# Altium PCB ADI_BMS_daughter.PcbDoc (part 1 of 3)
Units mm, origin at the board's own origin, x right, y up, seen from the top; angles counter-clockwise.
Board outline 140 x 50 mm, 4 copper layers (Top Layer, Layer 1, Layer 2, Bottom Layer), stack 1.586 mm thick; 306 components, 232 nets, 866 pads, 333 vias.
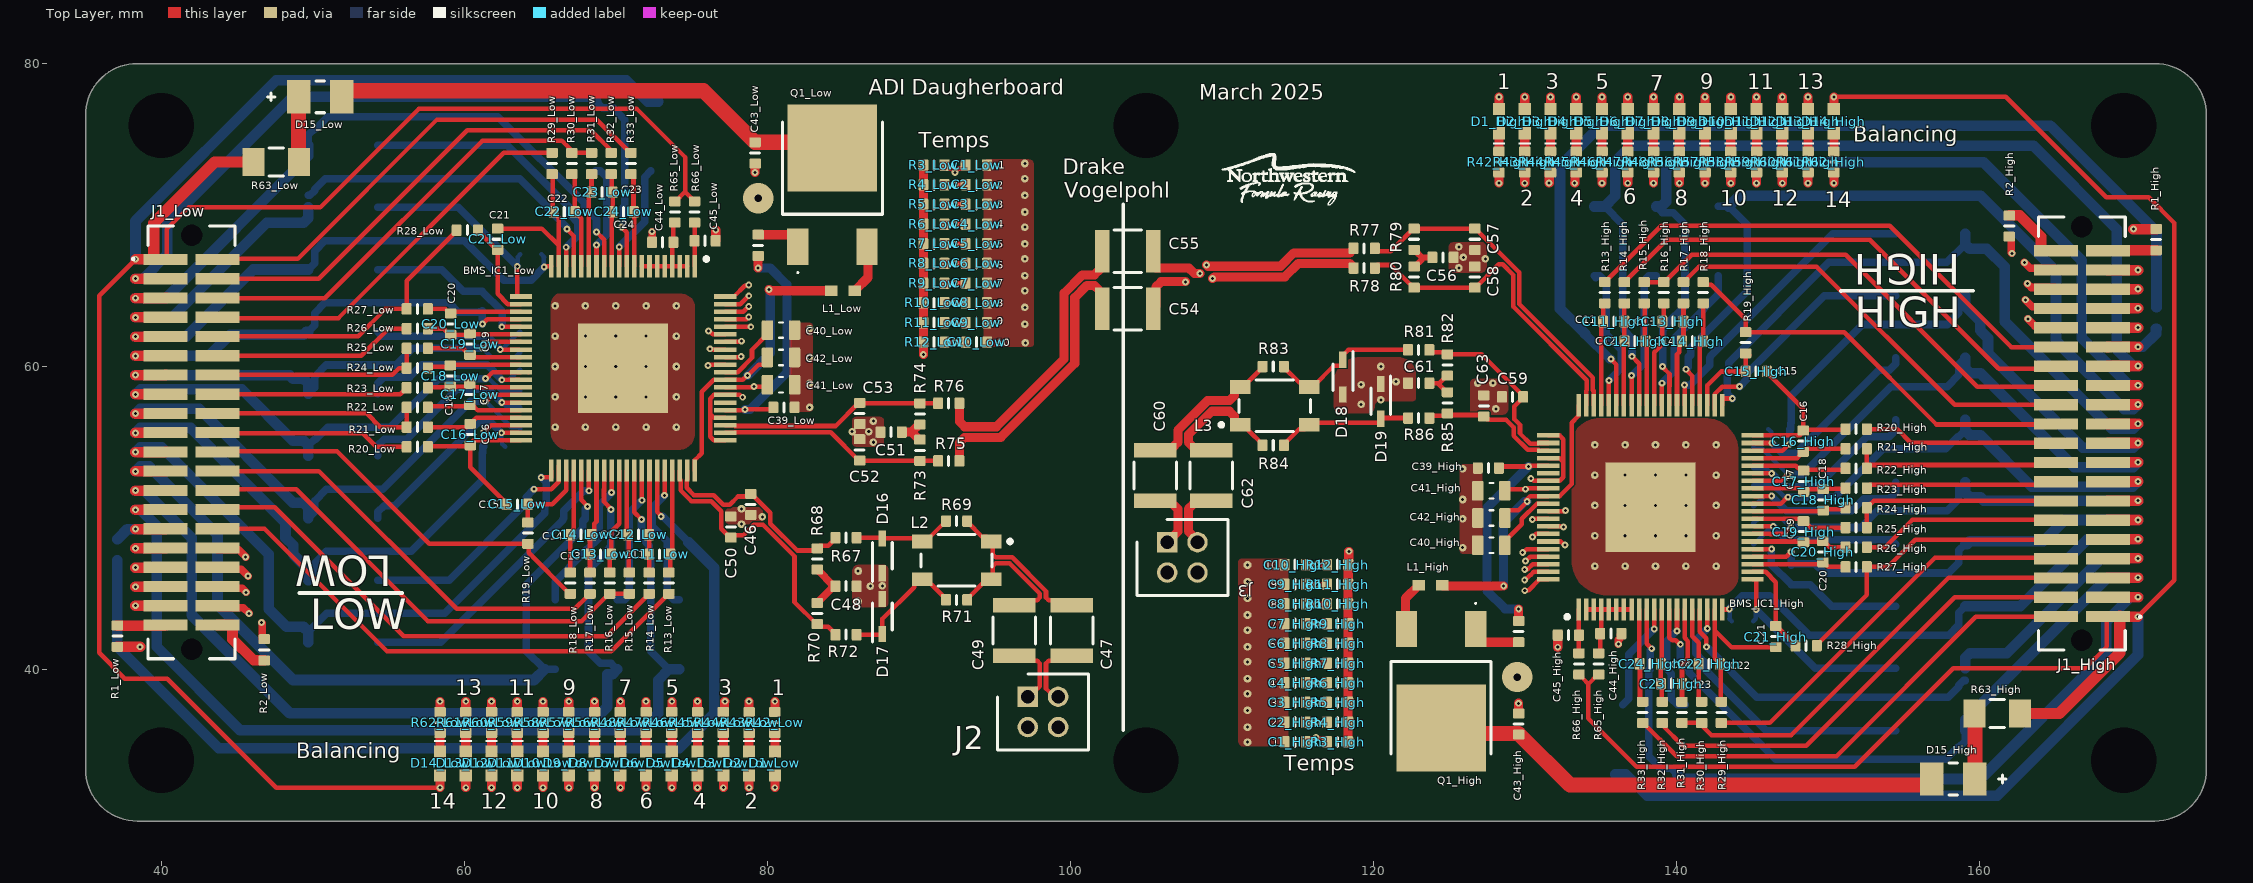
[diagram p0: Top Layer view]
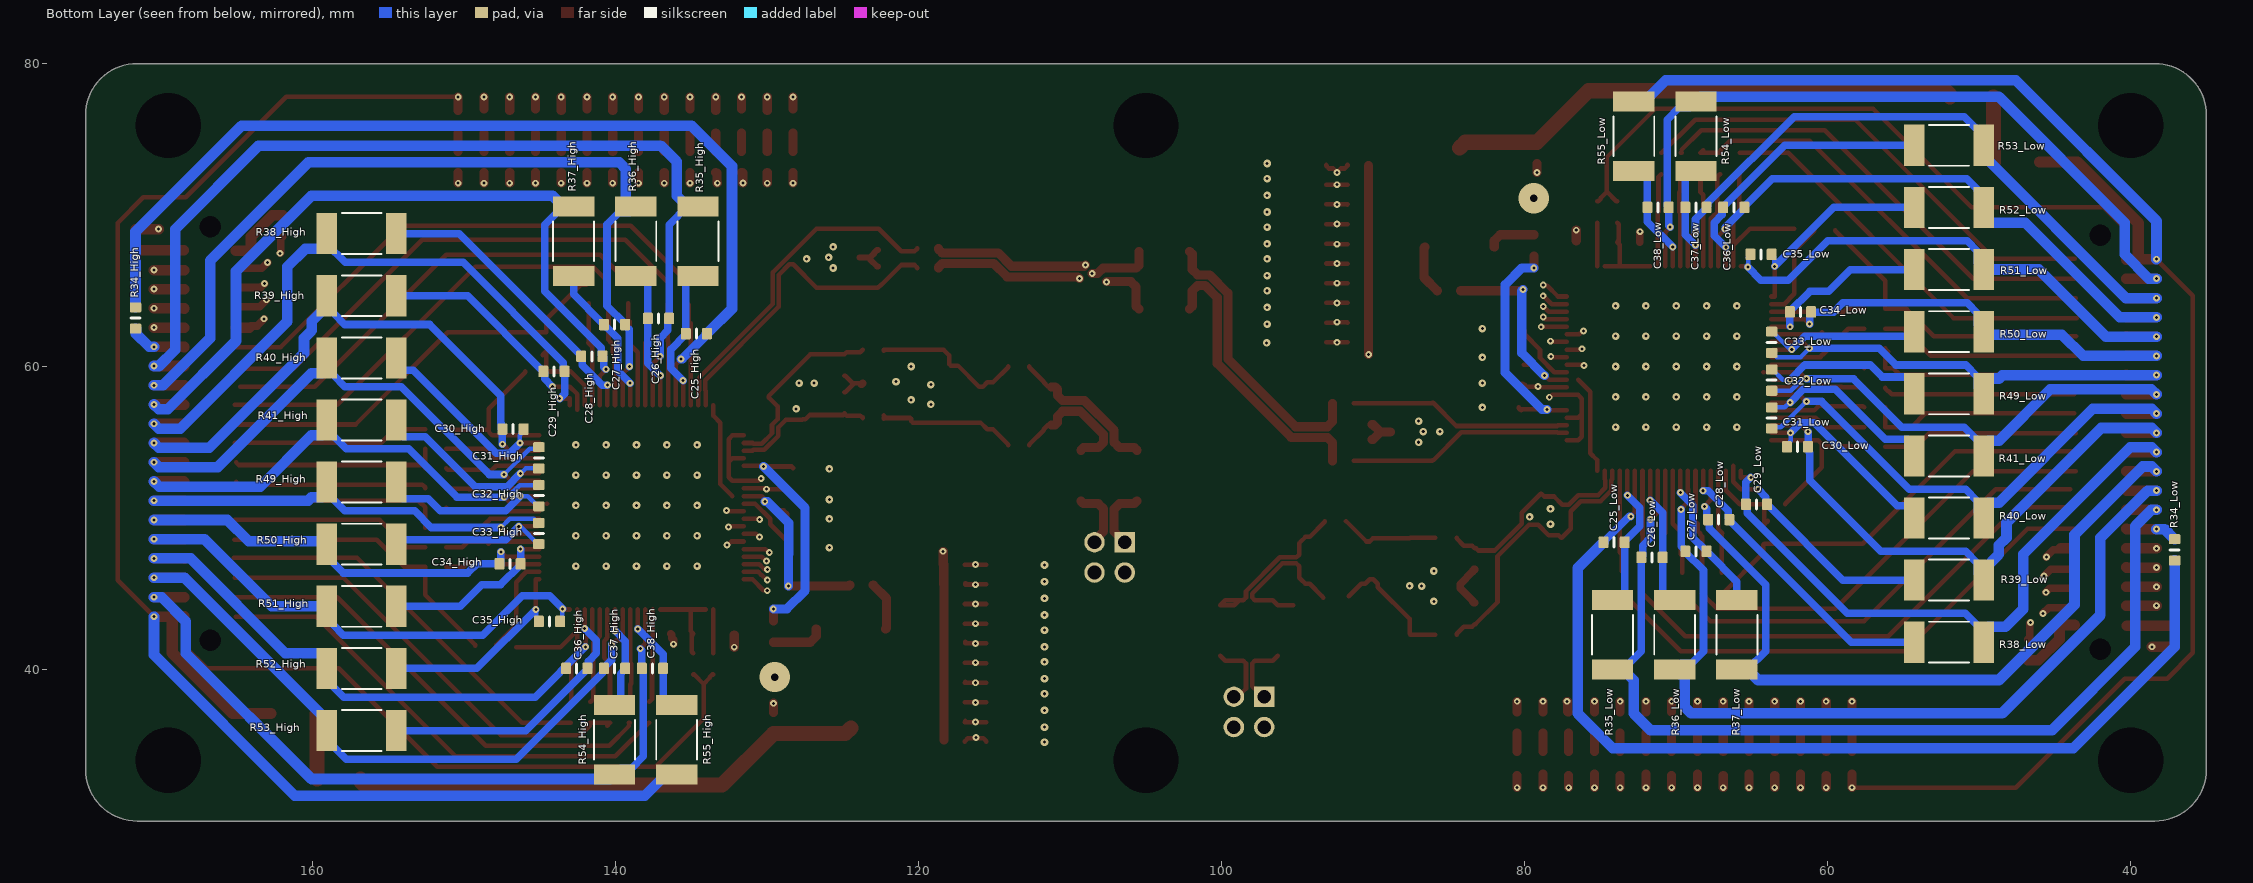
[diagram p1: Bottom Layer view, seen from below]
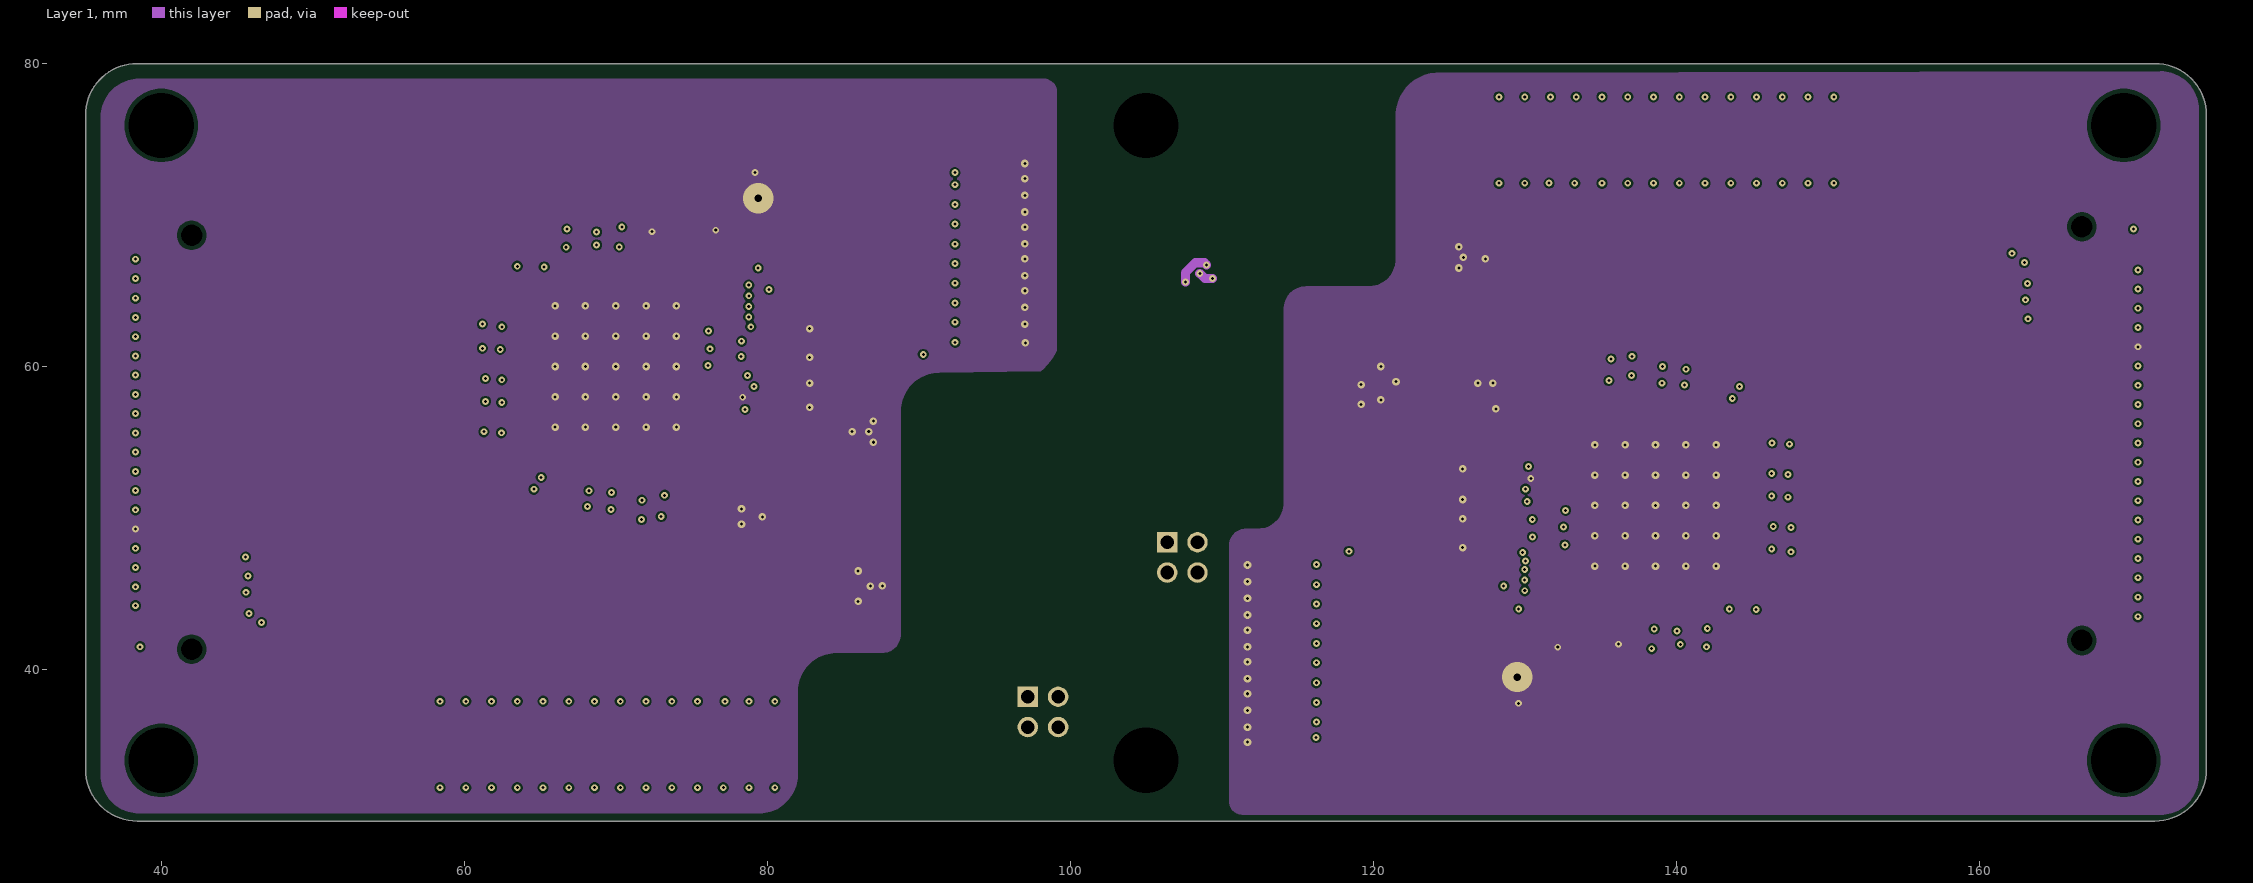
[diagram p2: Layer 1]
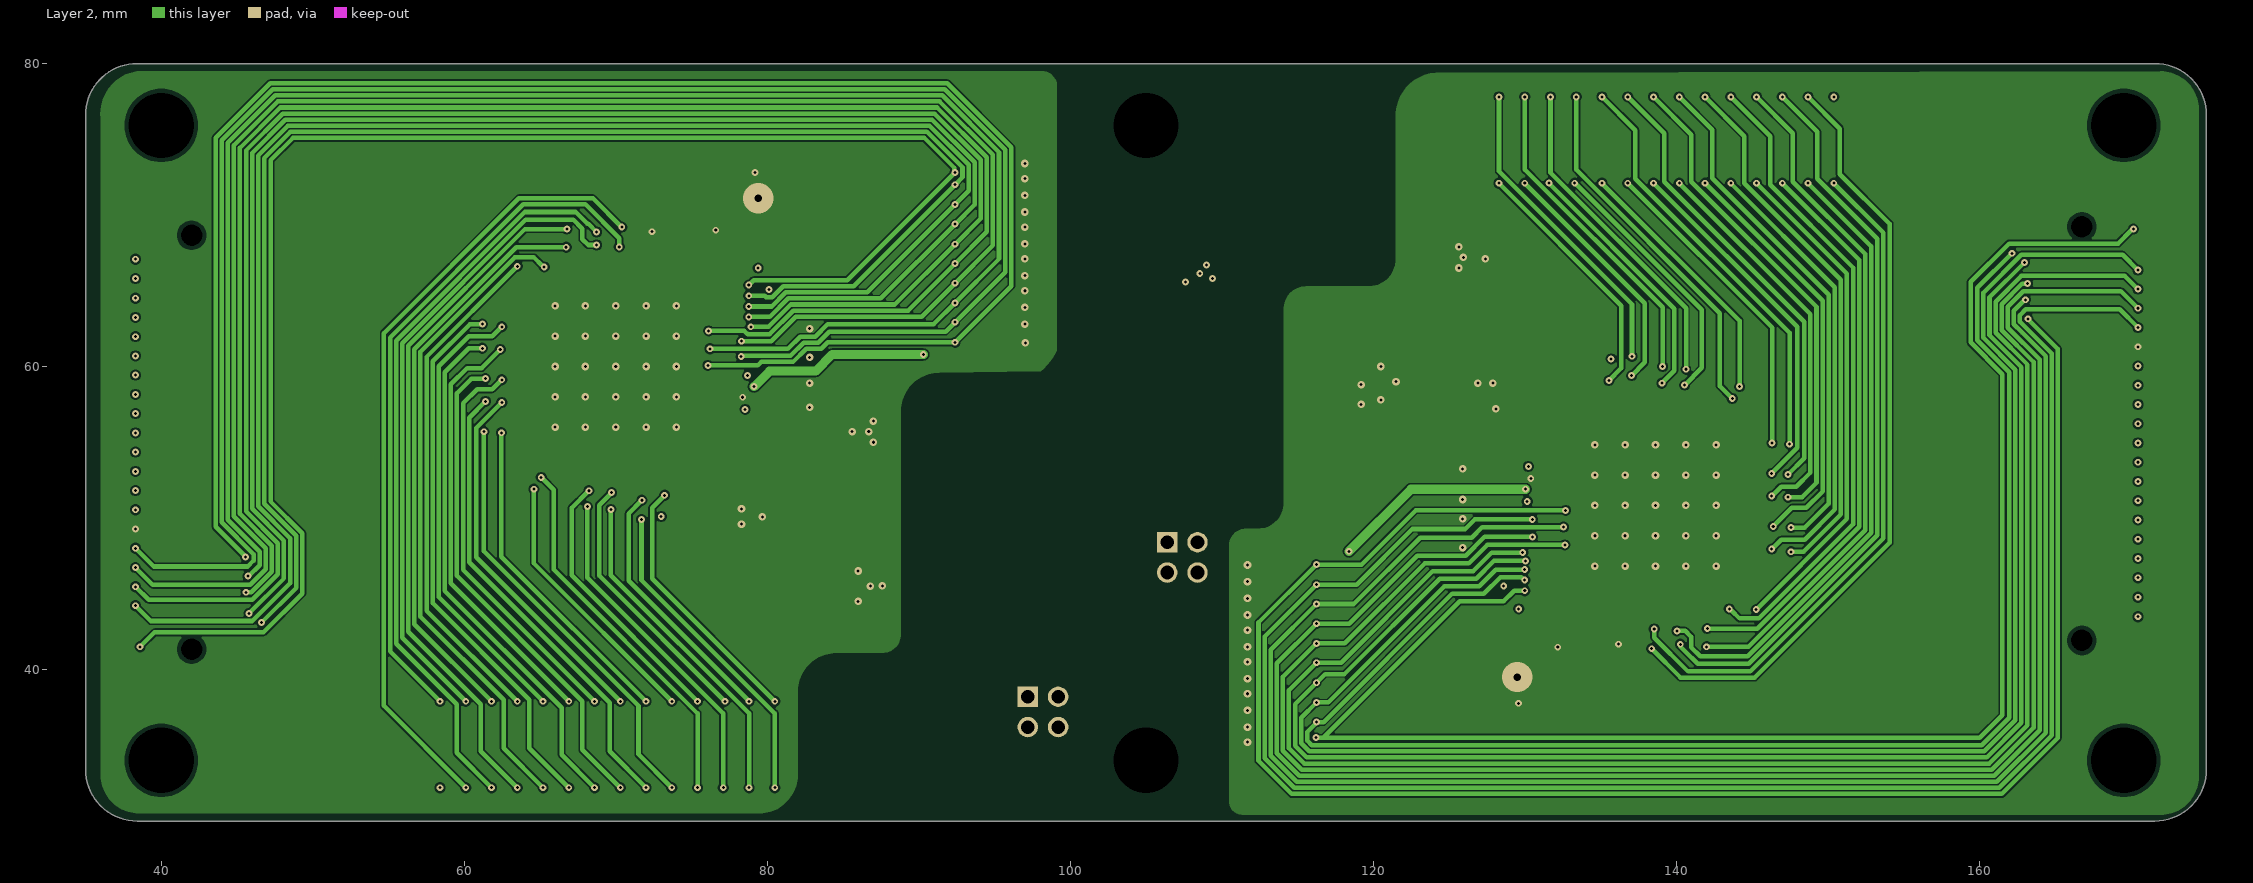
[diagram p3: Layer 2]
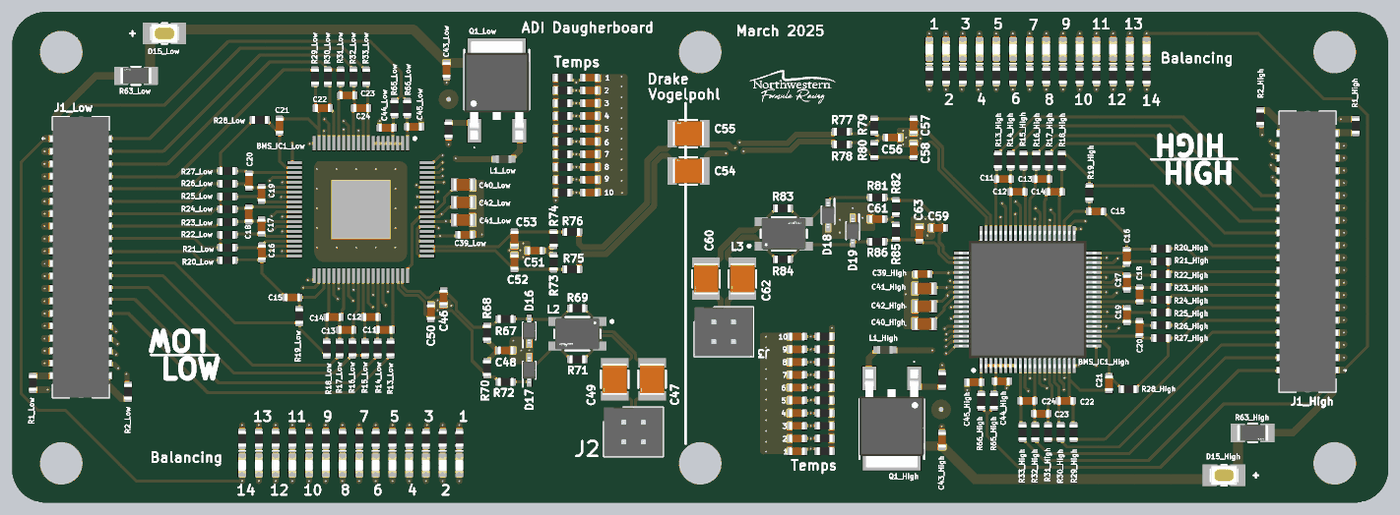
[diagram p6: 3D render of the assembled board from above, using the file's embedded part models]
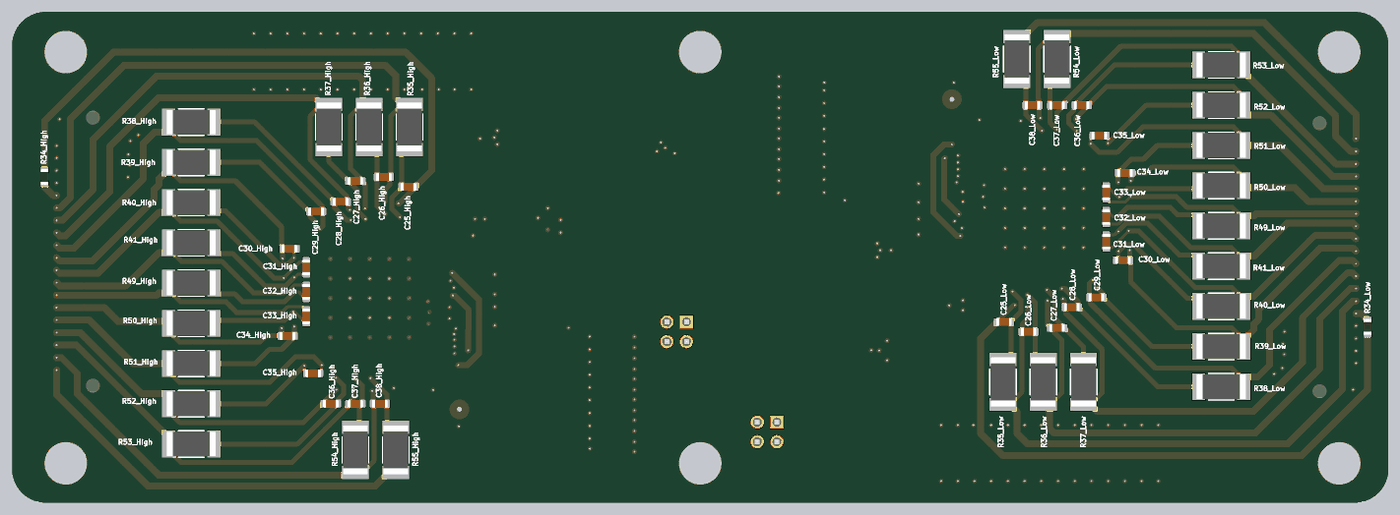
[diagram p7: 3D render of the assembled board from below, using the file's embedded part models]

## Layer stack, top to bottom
Top Solder: solder mask 0.0102, Solder Resist, Dk 3.5
Top Layer: signal copper 0.035
Dielectric 1: prepreg 0.2104, PP-023, Dk 4.5
Layer 1: signal copper 0.0152
Core: core 1.065, FR-4, Dk 4.8
Layer 2: signal copper 0.0152
Dielectric 2: prepreg 0.2104, PP-023, Dk 4.5
Bottom Layer: signal copper 0.035
Bottom Solder: solder mask 0.0102, Solder Resist, Dk 3.5

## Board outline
35,33.414 35,76.586 cw(c38.414,76.586) 38.414,80 171.586,80 cw(c171.586,76.586) 175,76.586 175,33.414 cw(c171.586,33.414) 171.586,30 38.414,30 cw(c38.414,33.414)

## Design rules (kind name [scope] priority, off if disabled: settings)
BoardOutlineClearance [All] p1: gap=0.2 ignorepadtopadclearanceinfootprint=FALSE
Clearance [All] p1: gap=0.102 ignorepadtopadclearanceinfootprint=FALSE except(0.127: Arc-Via Track-Via SMDPad-Via THPad-Via Via-Via Via-Fill Via-Poly Via-Region Via-Text; 0.25: Arc-Hole Track-Hole SMDPad-Hole THPad-Hole Via-Hole Fill-Hole Poly-Hole Region-Hole Text-Hole)
ComponentClearance [All] p1: gap=0.102 collisioncheckmode=3 verticalgap=0.102 showdistances=TRUE
DiffPairsRouting [All] p1: maxlimit=0.102 minlimit=0.102 mostfreqgap=0.102 toplayer_minwidth=0.102 toplayer_maxwidth=1816.048 toplayer_prefwidth=0.102 midlayer1_minwidth=0.102 midlayer1_maxwidth=1816.048 midlayer1_prefwidth=0.102 midlayer2_minwidth=0.102 midlayer2_maxwidth=1816.048 midlayer2_prefwidth=0.102 bottomlayer_minwidth=0.102 bottomlayer_maxwidth=1816.048 bottomlayer_prefwidth=0.102 maxuncoupledlength=12.7
Height [All] p1: minheight=0 maxheight=1816.048 prefheight=12.7
HoleSize [All] p1: absolutevalues=TRUE maxlimit=6.3 minlimit=0.2 maxpercent=80.000 minpercent=20.000
HoleToHoleClearance [All] p1: gap=0.25 allowstackedmicrovias=FALSE
MinimumAnnularRing [All] p1: minimumring=0.076
MinimumSolderMaskSliver [All] p1: minsoldermaskwidth=0
PlaneClearance [All] p1: clearance=0.102
PlaneConnect PlaneConnectPowerPads [InPadClass('PowerPads')] p1: planeconnectstyle=Direct reliefexpansion=0.508 reliefentries=4 reliefconductorwidth=0.254 reliefairgap=0.254
PlaneConnect [All] p2: pad.planeconnectstyle=Relief pad.reliefexpansion=0.3 pad.reliefentries=4 pad.reliefconductorwidth=0.102 pad.reliefairgap=0.102 via.planeconnectstyle=Direct via.reliefexpansion=0.3 via.reliefentries=4 via.reliefconductorwidth=0.127 via.reliefairgap=0.127
PolygonConnect PolygonConnectPowerPads [All vs (InPadClass('PowerPads'))] p1: connectstyle=Direct reliefconductorwidth=0.254 reliefentries=4 polygonreliefangle="90 Angle" airgapwidth=0.254
PolygonConnect [All] p2: thpad.connectstyle=Relief thpad.reliefconductorwidth=0.102 thpad.reliefentries=4 thpad.polygonreliefangle="90 Angle" thpad.airgapwidth=0.102 smdpad.connectstyle=Relief smdpad.reliefconductorwidth=0.102 smdpad.reliefentries=4 smdpad.polygonreliefangle="90 Angle" smdpad.airgapwidth=0.102 via.connectstyle=Direct via.reliefconductorwidth=0.127 via.reliefentries=4 via.polygonreliefangle="90 Angle" via.airgapwidth=0.127
RoutingVias [All] p1: holewidth=0.2 width=0.45 viastyle="Through Hole" minholewidth=0.2 minwidth=0.45 maxholewidth=6.3 maxwidth=6.55
SilkToSilkClearance [All] p1: silktosilkclearance=0
SilkToSolderMaskClearance [IsPad] p1: minsilkscreentomaskgap=0.102 clearancetoexposedcopper=TRUE
SolderMaskExpansion [All] p1: expansion=0.075 istentingtop=FALSE
Width [All] p1: maxlimit=1816.048 minlimit=0.102 preferedwidth=0.3 minimp=50.000000 maximp=50.000000 favimp=50.000000
20 further rules are at their usual default settings.

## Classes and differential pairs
channel class 1_ADI_BMS_daughter_half: High Low
component class Low: "           " BMS_IC1_Low C1_Low C2_Low C3_Low C4_Low C5_Low C6_Low C7_Low C8_Low C9_Low C10_Low C11_Low C12_Low C13_Low C14_Low C15_Low C16_Low C17_Low C18_Low C19_Low C20_Low C21_Low C22_Low C23_Low C24_Low C25_Low C26_Low C27_Low C28_Low C29_Low C30_Low C31_Low C32_Low C33_Low C34_Low C35_Low C36_Low C37_Low C38_Low C39_Low C40_Low C41_Low C42_Low C43_Low C44_Low C45_Low D1_Low D2_Low D3_Low D4_Low D5_Low D6_Low D7_Low D8_Low D9_Low D10_Low D11_Low D12_Low D13_Low D14_Low D15_Low J1_Low L1_Low Q1_Low R1_Low R2_Low R3_Low R4_Low R5_Low R6_Low R7_Low R8_Low R9_Low R10_Low R11_Low R12_Low R13_Low R14_Low R15_Low R16_Low R17_Low R18_Low R19_Low R20_Low R21_Low R22_Low R23_Low R24_Low R25_Low R26_Low R27_Low R28_Low R29_Low R30_Low R31_Low R32_Low R33_Low R34_Low R35_Low R36_Low R37_Low R38_Low R39_Low R40_Low R41_Low R42_Low R43_Low R44_Low R45_Low R46_Low R47_Low R48_Low R49_Low R50_Low R51_Low R52_Low R53_Low R54_Low R55_Low R56_Low R57_Low R58_Low R59_Low R60_Low R61_Low R62_Low R63_Low R65_Low R66_Low
component class High: "           " BMS_IC1_High C1_High C2_High C3_High C4_High C5_High C6_High C7_High C8_High C9_High C10_High C11_High C12_High C13_High C14_High C15_High C16_High C17_High C18_High C19_High C20_High C21_High C22_High C23_High C24_High C25_High C26_High C27_High C28_High C29_High C30_High C31_High C32_High C33_High C34_High C35_High C36_High C37_High C38_High C39_High C40_High C41_High C42_High C43_High C44_High C45_High D1_High D2_High D3_High D4_High D5_High D6_High D7_High D8_High D9_High D10_High D11_High D12_High D13_High D14_High D15_High J1_High L1_High Q1_High R1_High R2_High R3_High R4_High R5_High R6_High R7_High R8_High R9_High R10_High R11_High R12_High R13_High R14_High R15_High R16_High R17_High R18_High R19_High R20_High R21_High R22_High R23_High R24_High R25_High R26_High R27_High R28_High R29_High R30_High R31_High R32_High R33_High R34_High R35_High R36_High R37_High R38_High R39_High R40_High R41_High R42_High R43_High R44_High R45_High R46_High R47_High R48_High R49_High R50_High R51_High R52_High R53_High R54_High R55_High R56_High R57_High R58_High R59_High R60_High R61_High R62_High R63_High R65_High R66_High
component class 0_ADI_BMS_daughter_Overview: C46 C47 C48 C49 C50 C51 C52 C53 C54 C55 C56 C57 C58 C59 C60 C61 C62 C63 D16 D17 D18 D19 J2 J3 L2 L3 R67 R68 R69 R70 R71 R72 R73 R74 R75 R77 R78 R79 R80 R81 R82 R83 R84 R85 R86
differential pair IB_Low_Intr: +IB_Low_Intr_P -IB_Low_Intr_N
differential pair IB_High_Iso: +IB_High_Iso_P -IB_High_Iso_N
differential pair IB_High_CMC: +IB_High_CMC_P -IB_High_CMC_N
differential pair IA_Low_Iso: +IA_Low_Iso_P -IA_Low_Iso_N
differential pair IA_Low_CMC: +IA_Low_CMC_P -IA_Low_CMC_N
differential pair IA_High_Intr: +IA_High_Intr_P -IA_High_Intr_N
differential pair IB_Out: +IB_Out_P -IB_Out_N
differential pair IB_Low: +IB_Low_P -IB_Low_N
differential pair IB_High: +IB_High_P -IB_High_N
differential pair IA_Out: +IA_Out_P -IA_Out_N
differential pair IA_Low: +IA_Low_P -IA_Low_N
differential pair IA_High: +IA_High_P -IA_High_N

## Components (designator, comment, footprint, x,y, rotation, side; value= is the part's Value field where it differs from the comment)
BMS_IC1_High "ADBMS6830BCSWZ" QFP50P1400X1400X160-81N 138.3,50.7 r90 top (schematic designator BMS_IC1)
BMS_IC1_Low "ADBMS6830BCSWZ" QFP50P1400X1400X160-81N 70.479,59.871 r270 top locked (schematic designator BMS_IC1)
C1_High "0.1u" CAPC0603(1608)100_L 114.85,35.225 r180 top (schematic designator C1)
C1_Low "0.1u" CAPC0603(1608)100_L 93.8,73.3 r0 top (schematic designator C1)
C2_High "0.1u" CAPC0603(1608)100_L 114.85,36.525 r180 top (schematic designator C2)
C2_Low "0.1u" CAPC0603(1608)100_L 93.8,72 r0 top (schematic designator C2)
C3_High "0.1u" CAPC0603(1608)100_L 114.85,37.825 r180 top (schematic designator C3)
C3_Low "0.1u" CAPC0603(1608)100_L 93.8,70.7 r0 top (schematic designator C3)
C4_High "0.1u" CAPC0603(1608)100_L 114.85,39.125 r180 top (schematic designator C4)
C4_Low "0.1u" CAPC0603(1608)100_L 93.8,69.4 r0 top (schematic designator C4)
C5_High "0.1u" CAPC0603(1608)100_L 114.85,40.425 r180 top (schematic designator C5)
C5_Low "0.1u" CAPC0603(1608)100_L 93.8,68.1 r0 top (schematic designator C5)
C6_High "0.1u" CAPC0603(1608)100_L 114.85,41.725 r180 top (schematic designator C6)
C6_Low "0.1u" CAPC0603(1608)100_L 93.8,66.8 r0 top (schematic designator C6)
C7_High "0.1u" CAPC0603(1608)100_L 114.85,43.025 r180 top (schematic designator C7)
C7_Low "0.1u" CAPC0603(1608)100_L 93.8,65.5 r0 top (schematic designator C7)
C8_High "0.1u" CAPC0603(1608)100_L 114.85,44.325 r180 top (schematic designator C8)
C8_Low "0.1u" CAPC0603(1608)100_L 93.8,64.2 r0 top (schematic designator C8)
C9_High "0.1u" CAPC0603(1608)100_L 114.85,45.625 r180 top (schematic designator C9)
C9_Low "0.1u" CAPC0603(1608)100_L 93.8,62.9 r0 top (schematic designator C9)
C10_High "0.1u" CAPC0603(1608)100_L 114.85,46.925 r180 top (schematic designator C10)
C10_Low "0.1u" CAPC0603(1608)100_L 93.8,61.6 r0 top (schematic designator C10)
C11_High "C1608X7R2A103K080AA" CAPC0603(1608)100_L 135.879,62.971 r0 top value=10n (schematic designator C11)
C11_Low "C1608X7R2A103K080AA" CAPC0603(1608)100_L 72.9,47.6 r180 top value=10n (schematic designator C11)
C12_High "C1608X7R2A103K080AA" CAPC0603(1608)100_L 137.279,61.671 r0 top value=10n (schematic designator C12)
C12_Low "C1608X7R2A103K080AA" CAPC0603(1608)100_L 71.5,48.9 r180 top value=10n (schematic designator C12)
C13_High "C1608X7R2A103K080AA" CAPC0603(1608)100_L 139.779,62.971 r0 top value=10n (schematic designator C13)
C13_Low "C1608X7R2A103K080AA" CAPC0603(1608)100_L 69,47.6 r180 top value=10n (schematic designator C13)
C14_High "C1608X7R2A103K080AA" CAPC0603(1608)100_L 141.079,61.671 r0 top value=10n (schematic designator C14)
C14_Low "C1608X7R2A103K080AA" CAPC0603(1608)100_L 67.7,48.9 r180 top value=10n (schematic designator C14)
C15_High "C1608X7R2A103K080AA" CAPC0603(1608)100_L 145.279,59.671 r0 top value=10n (schematic designator C15)
C15_Low "C1608X7R2A103K080AA" CAPC0603(1608)100_L 63.5,50.9 r180 top value=10n (schematic designator C15)
C16_High "C1608X7R2A103K080AA" CAPC0603(1608)100_L 148.379,55.071 r270 top value=10n (schematic designator C16)
C16_Low "C1608X7R2A103K080AA" CAPC0603(1608)100_L 60.4,55.5 r90 top value=10n (schematic designator C16)
C17_High "C1608X7R2A103K080AA" CAPC0603(1608)100_L 148.404,52.421 r270 top value=10n (schematic designator C17)
C17_Low "C1608X7R2A103K080AA" CAPC0603(1608)100_L 60.375,58.15 r90 top value=10n (schematic designator C17)
C18_High "C1608X7R2A103K080AA" CAPC0603(1608)100_L 149.7,51.2 r270 top value=10n (schematic designator C18)
C18_Low "C1608X7R2A103K080AA" CAPC0603(1608)100_L 59.079,59.371 r90 top value=10n (schematic designator C18)
C19_High "C1608X7R2A103K080AA" CAPC0603(1608)100_L 148.4,49.1 r270 top value=10n (schematic designator C19)
C19_Low "C1608X7R2A103K080AA" CAPC0603(1608)100_L 60.379,61.471 r90 top value=10n (schematic designator C19)
C20_High "C1608X7R2A103K080AA" CAPC0603(1608)100_L 149.679,47.771 r270 top value=10n (schematic designator C20)
C20_Low "C1608X7R2A103K080AA" CAPC0603(1608)100_L 59.1,62.8 r90 top value=10n (schematic designator C20)
C21_High "C1608X7R2A103K080AA" CAPC0603(1608)100_L 146.579,42.171 r270 top value=10n (schematic designator C21)
C21_Low "C1608X7R2A103K080AA" CAPC0603(1608)100_L 62.2,68.4 r90 top value=10n (schematic designator C21)
C22_High "C1608X7R2A103K080AA" CAPC0603(1608)100_L 142.179,40.371 r180 top value=10n (schematic designator C22)
C22_Low "C1608X7R2A103K080AA" CAPC0603(1608)100_L 66.6,70.2 r0 top value=10n (schematic designator C22)
C23_High "C1608X7R2A103K080AA" CAPC0603(1608)100_L 139.679,39.071 r180 top value=10n (schematic designator C23)
C23_Low "C1608X7R2A103K080AA" CAPC0603(1608)100_L 69.1,71.5 r0 top value=10n (schematic designator C23)
C24_High "C1608X7R2A103K080AA" CAPC0603(1608)100_L 138.279,40.371 r180 top value=10n (schematic designator C24)
C24_Low "C1608X7R2A103K080AA" CAPC0603(1608)100_L 70.5,70.2 r0 top value=10n (schematic designator C24)
C25_High "0.1u" CAPC0603(1608)100_L 134.679,62.171 r0 bottom (schematic designator C25)
C25_Low "0.1u" CAPC0603(1608)100_L 74.1,48.4 r180 bottom (schematic designator C25)
C26_High "0.1u" CAPC0603(1608)100_L 137.179,63.171 r0 bottom (schematic designator C26)
C26_Low "0.1u" CAPC0603(1608)100_L 71.6,47.4 r180 bottom (schematic designator C26)
C27_High "0.1u" CAPC0603(1608)100_L 140.079,62.771 r0 bottom (schematic designator C27)
C27_Low "0.1u" CAPC0603(1608)100_L 68.7,47.8 r180 bottom (schematic designator C27)
C28_High "0.1u" CAPC0603(1608)100_L 141.579,60.671 r0 bottom (schematic designator C28)
C28_Low "0.1u" CAPC0603(1608)100_L 67.2,49.9 r180 bottom (schematic designator C28)
C29_High "0.1u" CAPC0603(1608)100_L 144.079,59.671 r0 bottom (schematic designator C29)
C29_Low "0.1u" CAPC0603(1608)100_L 64.7,50.9 r180 bottom (schematic designator C29)
C30_High "0.1u" CAPC0603(1608)100_L 146.779,55.871 r180 bottom (schematic designator C30)
C30_Low "0.1u" CAPC0603(1608)100_L 62,54.7 r0 bottom (schematic designator C30)
C31_High "0.1u" CAPC0603(1608)100_L 145.079,53.971 r270 bottom (schematic designator C31)
C31_Low "0.1u" CAPC0603(1608)100_L 63.7,56.6 r90 bottom (schematic designator C31)
C32_High "0.1u" CAPC0603(1608)100_L 145.079,51.471 r270 bottom (schematic designator C32)
C32_Low "0.1u" CAPC0603(1608)100_L 63.7,59.1 r90 bottom (schematic designator C32)
C33_High "0.1u" CAPC0603(1608)100_L 145.079,48.971 r270 bottom (schematic designator C33)
C33_Low "0.1u" CAPC0603(1608)100_L 63.7,61.6 r90 bottom (schematic designator C33)
C34_High "0.1u" CAPC0603(1608)100_L 146.979,46.971 r180 bottom (schematic designator C34)
C34_Low "0.1u" CAPC0603(1608)100_L 61.8,63.6 r0 bottom (schematic designator C34)
C35_High "0.1u" CAPC0603(1608)100_L 144.379,43.171 r0 bottom (schematic designator C35)
C35_Low "0.1u" CAPC0603(1608)100_L 64.4,67.4 r180 bottom (schematic designator C35)
C36_High "0.1u" CAPC0603(1608)100_L 142.579,40.071 r180 bottom (schematic designator C36)
C36_Low "0.1u" CAPC0603(1608)100_L 66.2,70.5 r0 bottom (schematic designator C36)
C37_High "0.1u" CAPC0603(1608)100_L 140.079,40.071 r180 bottom (schematic designator C37)
C37_Low "0.1u" CAPC0603(1608)100_L 68.7,70.5 r0 bottom (schematic designator C37)
C38_High "0.1u" CAPC0603(1608)100_L 137.579,40.071 r180 bottom (schematic designator C38)
C38_Low "0.1u" CAPC0603(1608)100_L 71.2,70.5 r0 bottom (schematic designator C38)
C39_High "C1608X7R2A103K080AA" CAPC0603(1608)100_L 127.6,53.3 r0 top value=10n (schematic designator C39)
C39_Low "C1608X7R2A103K080AA" CAPC0603(1608)100_L 81.1,57.3 r180 top value=10n (schematic designator C39)
C40_High "1u" CAPC0805(2012)145_L 127.8,48.2 r0 top (schematic designator C40)
C40_Low "1u" CAPC0805(2012)145_L 80.9,62.4 r180 top (schematic designator C40)
C41_High "1u" CAPC0805(2012)145_L 127.8,51.8 r0 top (schematic designator C41)
C41_Low "1u" CAPC0805(2012)145_L 80.9,58.8 r180 top (schematic designator C41)
C42_High "1u" CAPC0805(2012)145_L 127.8,50 r0 top (schematic designator C42)
C42_Low "1u" CAPC0805(2012)145_L 80.9,60.6 r180 top (schematic designator C42)
C43_High "C1608X7R2A103K080AA" CAPC0603(1608)100_L 129.6,36.4 r90 top value=10n (schematic designator C43)
C43_Low "C1608X7R2A103K080AA" CAPC0603(1608)100_L 79.2,74.1 r270 top value=10n (schematic designator C43)
C44_High "C1608X7R2A103K080AA" CAPC0603(1608)100_L 135.679,42.371 r180 top value=10n (schematic designator C44)
C44_Low "C1608X7R2A103K080AA" CAPC0603(1608)100_L 73.1,68.2 r0 top value=10n (schematic designator C44)
C45_High "C1608X7R2A103K080AA" CAPC0603(1608)100_L 132.879,42.271 r180 top value=10n (schematic designator C45)
C45_Low "C1608X7R2A103K080AA" CAPC0603(1608)100_L 75.9,68.3 r0 top value=10n (schematic designator C45)
C46 "CGA3E2C0G2A221J080AA" CAPC0603(1608)100_L 78.9,50.9 r270 top value=220pF
C47 "22n" FP-C3225-250-0_4-IPC_B 100.1,42.575 r270 top
C48 "0.1u" CAPC0603(1608)100_L 85.2,45.5 r0 top
C49 "22n" FP-C3225-250-0_4-IPC_B 96.3,42.575 r270 top
C50 "CGA3E2C0G2A221J080AA" CAPC0603(1608)100_L 77.6,49.4 r270 top value=220pF
C51 "0.1u" CAPC0603(1608)100_L 88.179,55.671 r0 top
C52 "CGA3E2C0G2A221J080AA" CAPC0603(1608)100_L 86.1,54.5 r90 top value=220pF
C53 "CGA3E2C0G2A221J080AA" CAPC0603(1608)100_L 86.1,56.9 r90 top value=220pF
C54 "22n" FP-C3225-250-0_4-IPC_B 103.8,63.8 r180 top
C55 "22n" FP-C3225-250-0_4-IPC_B 103.8,67.6 r180 top
C56 "0.1u" CAPC0603(1608)100_L 124.6,67.2 r0 top
C57 "CGA3E2C0G2A221J080AA" CAPC0603(1608)100_L 126.7,68.4 r270 top value=220pF
C58 "CGA3E2C0G2A221J080AA" CAPC0603(1608)100_L 126.7,65.9 r270 top value=220pF
C59 "CGA3E2C0G2A221J080AA" CAPC0603(1608)100_L 129.2,58 r180 top value=220pF
C60 "22n" FP-C3225-250-0_4-IPC_B 105.6,52.8 r270 top
C61 "0.1u" CAPC0603(1608)100_L 123,58.9 r180 top
C62 "22n" FP-C3225-250-0_4-IPC_B 109.3,52.8 r270 top
C63 "CGA3E2C0G2A221J080AA" CAPC0603(1608)100_L 127.3,57.4 r270 top value=220pF
D1_High "150060RS75000" WL-SMCW_0603_150060xx75000 128.3,76.2 r90 top (schematic designator D1)
D1_Low "150060RS75000" WL-SMCW_0603_150060xx75000 80.5,33.8 r270 top (schematic designator D1)
D2_High "150060RS75000" WL-SMCW_0603_150060xx75000 130,76.2 r90 top (schematic designator D2)
D2_Low "150060RS75000" WL-SMCW_0603_150060xx75000 78.8,33.8 r270 top (schematic designator D2)
D3_High "150060RS75000" WL-SMCW_0603_150060xx75000 131.7,76.2 r90 top (schematic designator D3)
D3_Low "150060RS75000" WL-SMCW_0603_150060xx75000 77.1,33.8 r270 top (schematic designator D3)
D4_High "150060RS75000" WL-SMCW_0603_150060xx75000 133.4,76.2 r90 top (schematic designator D4)
D4_Low "150060RS75000" WL-SMCW_0603_150060xx75000 75.4,33.8 r270 top (schematic designator D4)
D5_High "150060RS75000" WL-SMCW_0603_150060xx75000 135.1,76.2 r90 top (schematic designator D5)
D5_Low "150060RS75000" WL-SMCW_0603_150060xx75000 73.7,33.8 r270 top (schematic designator D5)
D6_High "150060RS75000" WL-SMCW_0603_150060xx75000 136.8,76.2 r90 top (schematic designator D6)
D6_Low "150060RS75000" WL-SMCW_0603_150060xx75000 72,33.8 r270 top (schematic designator D6)
D7_High "150060RS75000" WL-SMCW_0603_150060xx75000 138.5,76.2 r90 top (schematic designator D7)
D7_Low "150060RS75000" WL-SMCW_0603_150060xx75000 70.3,33.8 r270 top (schematic designator D7)
D8_High "150060RS75000" WL-SMCW_0603_150060xx75000 140.2,76.2 r90 top (schematic designator D8)
D8_Low "150060RS75000" WL-SMCW_0603_150060xx75000 68.6,33.8 r270 top (schematic designator D8)
D9_High "150060RS75000" WL-SMCW_0603_150060xx75000 141.9,76.2 r90 top (schematic designator D9)
D9_Low "150060RS75000" WL-SMCW_0603_150060xx75000 66.9,33.8 r270 top (schematic designator D9)
D10_High "150060RS75000" WL-SMCW_0603_150060xx75000 143.6,76.2 r90 top (schematic designator D10)
D10_Low "150060RS75000" WL-SMCW_0603_150060xx75000 65.2,33.8 r270 top (schematic designator D10)
D11_High "150060RS75000" WL-SMCW_0603_150060xx75000 145.3,76.2 r90 top (schematic designator D11)
D11_Low "150060RS75000" WL-SMCW_0603_150060xx75000 63.5,33.8 r270 top (schematic designator D11)
D12_High "150060RS75000" WL-SMCW_0603_150060xx75000 147,76.2 r90 top (schematic designator D12)
D12_Low "150060RS75000" WL-SMCW_0603_150060xx75000 61.8,33.8 r270 top (schematic designator D12)
D13_High "150060RS75000" WL-SMCW_0603_150060xx75000 148.7,76.2 r90 top (schematic designator D13)
D13_Low "150060RS75000" WL-SMCW_0603_150060xx75000 60.1,33.8 r270 top (schematic designator D13)
D14_High "150060RS75000" WL-SMCW_0603_150060xx75000 150.4,76.2 r90 top (schematic designator D14)
D14_Low "150060RS75000" WL-SMCW_0603_150060xx75000 58.4,33.8 r270 top (schematic designator D14)
D15_High "Amber LED" FP-CLM3C-AKW-MFG 158.279,32.771 r180 top (schematic designator D15)
D15_Low "Amber LED" FP-CLM3C-AKW-MFG 50.5,77.8 r0 top (schematic designator D15)
D16 "SD12C-01FTG" SOD2613X114N 87.6,47.5 r90 top
D17 "SD12C-01FTG" SOD2613X114N 87.6,43.5 r90 top
D18 "SD12C-01FTG" SOD2613X114N 118,59.3 r270 top
D19 "SD12C-01FTG" SOD2613X114N 120.5,57.7 r270 top
J1_High "TFM-120-02-L-D-A-TR" TFM12002LDATR 166.779,55.571 r90 top (schematic designator J1)
J1_Low "TFM-120-02-L-D-A-TR" TFM12002LDATR 42,55 r270 top locked (schematic designator J1)
J2 "DF11-4DP-2DSA_01_" SHDR4W50P200_2X2_600X500X660P 97.2,38.2 r180 top
J3 "DF11-4DP-2DSA_01_" SHDR4W50P200_2X2_600X500X660P 106.4,48.4 r180 top
L1_High "742792693" SMD-0603 123.779,45.571 r0 top (schematic designator L1)
L1_Low "742792693" SMD-0603 85,65 r180 top (schematic designator L1)
L2 "DLW43SH101XK2L" FP-DLW43-0_2-t2_6-e0_6-MFG 92.5,47.2 r180 top
L3 "DLW43SH101XK2L" FP-DLW43-0_2-t2_6-e0_6-MFG 113.5,57.4 r0 top
Q1_High "MJD31CAJ" MJD31CAJ 124.479,38.571 r180 top (schematic designator Q1)
Q1_Low "MJD31CAJ" MJD31CAJ 84.3,72 r0 top (schematic designator Q1)
R1_High "RMCF0603ZT0R00" RESC0603(1608)_L 171.679,68.371 r270 top value=0 (schematic designator R1)
R1_Low "RMCF0603ZT0R00" RESC0603(1608)_L 37.1,42.2 r90 top value=0 (schematic designator R1)
R2_High "RMCF0603ZT0R00" RESC0603(1608)_L 161.979,69.271 r90 top value=0 (schematic designator R2)
R2_Low "RMCF0603ZT0R00" RESC0603(1608)_L 46.8,41.3 r270 top value=0 (schematic designator R2)
R3_High "RT0603BRD0710KL" RESC0603(1608)_L 117.65,35.225 r0 top value=10k (schematic designator R3)
R3_Low "RT0603BRD0710KL" RESC0603(1608)_L 91,73.3 r180 top value=10k (schematic designator R3)
R4_High "RT0603BRD0710KL" RESC0603(1608)_L 117.65,36.525 r0 top value=10k (schematic designator R4)
R4_Low "RT0603BRD0710KL" RESC0603(1608)_L 91,72 r180 top value=10k (schematic designator R4)
R5_High "RT0603BRD0710KL" RESC0603(1608)_L 117.65,37.825 r0 top value=10k (schematic designator R5)
R5_Low "RT0603BRD0710KL" RESC0603(1608)_L 91,70.7 r180 top value=10k (schematic designator R5)
R6_High "RT0603BRD0710KL" RESC0603(1608)_L 117.65,39.125 r0 top value=10k (schematic designator R6)
R6_Low "RT0603BRD0710KL" RESC0603(1608)_L 91,69.4 r180 top value=10k (schematic designator R6)
R7_High "RT0603BRD0710KL" RESC0603(1608)_L 117.65,40.425 r0 top value=10k (schematic designator R7)
R7_Low "RT0603BRD0710KL" RESC0603(1608)_L 91,68.1 r180 top value=10k (schematic designator R7)
R8_High "RT0603BRD0710KL" RESC0603(1608)_L 117.65,41.725 r0 top value=10k (schematic designator R8)
R8_Low "RT0603BRD0710KL" RESC0603(1608)_L 91,66.8 r180 top value=10k (schematic designator R8)
R9_High "RT0603BRD0710KL" RESC0603(1608)_L 117.65,43.025 r0 top value=10k (schematic designator R9)
R9_Low "RT0603BRD0710KL" RESC0603(1608)_L 91,65.5 r180 top value=10k (schematic designator R9)
R10_High "RT0603BRD0710KL" RESC0603(1608)_L 117.65,44.325 r0 top value=10k (schematic designator R10)
R10_Low "RT0603BRD0710KL" RESC0603(1608)_L 91,64.2 r180 top value=10k (schematic designator R10)
R11_High "RT0603BRD0710KL" RESC0603(1608)_L 117.65,45.625 r0 top value=10k (schematic designator R11)
R11_Low "RT0603BRD0710KL" RESC0603(1608)_L 91,62.9 r180 top value=10k (schematic designator R11)
R12_High "RT0603BRD0710KL" RESC0603(1608)_L 117.65,46.925 r0 top value=10k (schematic designator R12)
R12_Low "RT0603BRD0710KL" RESC0603(1608)_L 91,61.6 r180 top value=10k (schematic designator R12)
R13_High "ESR03EZPF2000" RESC0603(1608)_L 135.279,64.871 r270 top value=200 (schematic designator R13)
R13_Low "ESR03EZPF2000" RESC0603(1608)_L 73.5,45.7 r90 top value=200 (schematic designator R13)
R14_High "ESR03EZPF2000" RESC0603(1608)_L 136.579,64.871 r270 top value=200 (schematic designator R14)
R14_Low "ESR03EZPF2000" RESC0603(1608)_L 72.2,45.7 r90 top value=200 (schematic designator R14)
R15_High "ESR03EZPF2000" RESC0603(1608)_L 137.879,64.871 r270 top value=200 (schematic designator R15)
R15_Low "ESR03EZPF2000" RESC0603(1608)_L 70.9,45.7 r90 top value=200 (schematic designator R15)
R16_High "ESR03EZPF2000" RESC0603(1608)_L 139.179,64.871 r270 top value=200 (schematic designator R16)
R16_Low "ESR03EZPF2000" RESC0603(1608)_L 69.6,45.7 r90 top value=200 (schematic designator R16)
R17_High "ESR03EZPF2000" RESC0603(1608)_L 140.479,64.871 r270 top value=200 (schematic designator R17)
R17_Low "ESR03EZPF2000" RESC0603(1608)_L 68.3,45.7 r90 top value=200 (schematic designator R17)
R18_High "ESR03EZPF2000" RESC0603(1608)_L 141.779,64.871 r270 top value=200 (schematic designator R18)
R18_Low "ESR03EZPF2000" RESC0603(1608)_L 67,45.7 r90 top value=200 (schematic designator R18)
R19_High "ESR03EZPF2000" RESC0603(1608)_L 144.579,61.571 r270 top value=200 (schematic designator R19)
R19_Low "ESR03EZPF2000" RESC0603(1608)_L 64.2,49 r90 top value=200 (schematic designator R19)
R20_High "ESR03EZPF2000" RESC0603(1608)_L 151.879,55.871 r180 top value=200 (schematic designator R20)
R20_Low "ESR03EZPF2000" RESC0603(1608)_L 56.9,54.7 r0 top value=200 (schematic designator R20)
R21_High "ESR03EZPF2000" RESC0603(1608)_L 151.879,54.571 r180 top value=200 (schematic designator R21)
R21_Low "ESR03EZPF2000" RESC0603(1608)_L 56.9,56 r0 top value=200 (schematic designator R21)
R22_High "ESR03EZPF2000" RESC0603(1608)_L 151.879,53.271 r180 top value=200 (schematic designator R22)
R22_Low "ESR03EZPF2000" RESC0603(1608)_L 56.9,57.3 r0 top value=200 (schematic designator R22)
R23_High "ESR03EZPF2000" RESC0603(1608)_L 151.879,51.971 r180 top value=200 (schematic designator R23)
R23_Low "ESR03EZPF2000" RESC0603(1608)_L 56.9,58.6 r0 top value=200 (schematic designator R23)
R24_High "ESR03EZPF2000" RESC0603(1608)_L 151.879,50.671 r180 top value=200 (schematic designator R24)
R24_Low "ESR03EZPF2000" RESC0603(1608)_L 56.9,59.9 r0 top value=200 (schematic designator R24)
R25_High "ESR03EZPF2000" RESC0603(1608)_L 151.879,49.371 r180 top value=200 (schematic designator R25)
R25_Low "ESR03EZPF2000" RESC0603(1608)_L 56.9,61.2 r0 top value=200 (schematic designator R25)
R26_High "ESR03EZPF2000" RESC0603(1608)_L 151.879,48.071 r180 top value=200 (schematic designator R26)
R26_Low "ESR03EZPF2000" RESC0603(1608)_L 56.9,62.5 r0 top value=200 (schematic designator R26)
R27_High "ESR03EZPF2000" RESC0603(1608)_L 151.879,46.771 r180 top value=200 (schematic designator R27)
R27_Low "ESR03EZPF2000" RESC0603(1608)_L 56.9,63.8 r0 top value=200 (schematic designator R27)
R28_High "ESR03EZPF2000" RESC0603(1608)_L 148.579,41.571 r180 top value=200 (schematic designator R28)
R28_Low "ESR03EZPF2000" RESC0603(1608)_L 60.2,69 r0 top value=200 (schematic designator R28)
R29_High "ESR03EZPF2000" RESC0603(1608)_L 142.979,37.171 r90 top value=200 (schematic designator R29)
R29_Low "ESR03EZPF2000" RESC0603(1608)_L 65.8,73.4 r270 top value=200 (schematic designator R29)
R30_High "ESR03EZPF2000" RESC0603(1608)_L 141.679,37.171 r90 top value=200 (schematic designator R30)
R30_Low "ESR03EZPF2000" RESC0603(1608)_L 67.1,73.4 r270 top value=200 (schematic designator R30)
R31_High "ESR03EZPF2000" RESC0603(1608)_L 140.379,37.171 r90 top value=200 (schematic designator R31)
R31_Low "ESR03EZPF2000" RESC0603(1608)_L 68.4,73.4 r270 top value=200 (schematic designator R31)
R32_High "ESR03EZPF2000" RESC0603(1608)_L 139.079,37.171 r90 top value=200 (schematic designator R32)
R32_Low "ESR03EZPF2000" RESC0603(1608)_L 69.7,73.4 r270 top value=200 (schematic designator R32)
R33_High "ESR03EZPF2000" RESC0603(1608)_L 137.779,37.171 r90 top value=200 (schematic designator R33)
R33_Low "ESR03EZPF2000" RESC0603(1608)_L 71,73.4 r270 top value=200 (schematic designator R33)
R34_High "RMCF0603ZT0R00" RESC0603(1608)_L 171.7,63.2 r270 bottom value=0 (schematic designator R34)
R34_Low "RMCF0603ZT0R00" RESC0603(1608)_L 37.1,47.9 r90 bottom value=0 (schematic designator R34)
R35_High "RMCP2010FT20R0" RESC5025X70N 134.579,68.271 r270 bottom value=20 (schematic designator R35)
R35_Low "RMCP2010FT20R0" RESC5025X70N 74.2,42.3 r90 bottom value=20 (schematic designator R35)
R36_High "RMCP2010FT20R0" RESC5025X70N 138.679,68.271 r270 bottom value=20 (schematic designator R36)
R36_Low "RMCP2010FT20R0" RESC5025X70N 70.1,42.3 r90 bottom value=20 (schematic designator R36)
R37_High "RMCP2010FT20R0" RESC5025X70N 142.779,68.271 r270 bottom value=20 (schematic designator R37)
R37_Low "RMCP2010FT20R0" RESC5025X70N 66,42.3 r90 bottom value=20 (schematic designator R37)
R38_High "RMCP2010FT20R0" RESC5025X70N 156.779,68.771 r180 bottom value=20 (schematic designator R38)
R38_Low "RMCP2010FT20R0" RESC5025X70N 52,41.8 r0 bottom value=20 (schematic designator R38)
R39_High "RMCP2010FT20R0" RESC5025X70N 156.779,64.671 r180 bottom value=20 (schematic designator R39)
R39_Low "RMCP2010FT20R0" RESC5025X70N 52,45.9 r0 bottom value=20 (schematic designator R39)
R40_High "RMCP2010FT20R0" RESC5025X70N 156.779,60.571 r180 bottom value=20 (schematic designator R40)
R40_Low "RMCP2010FT20R0" RESC5025X70N 52,50 r0 bottom value=20 (schematic designator R40)
R41_High "RMCP2010FT20R0" RESC5025X70N 156.779,56.471 r180 bottom value=20 (schematic designator R41)
R41_Low "RMCP2010FT20R0" RESC5025X70N 52,54.1 r0 bottom value=20 (schematic designator R41)
R42_High "100" RESC0603(1608)_L 128.3,73.5 r270 top (schematic designator R42)
R42_Low "100" RESC0603(1608)_L 80.5,36.5 r90 top (schematic designator R42)
R43_High "100" RESC0603(1608)_L 130,73.5 r270 top (schematic designator R43)
R43_Low "100" RESC0603(1608)_L 78.8,36.5 r90 top (schematic designator R43)
R44_High "100" RESC0603(1608)_L 131.7,73.5 r270 top (schematic designator R44)
R44_Low "100" RESC0603(1608)_L 77.1,36.5 r90 top (schematic designator R44)
R45_High "100" RESC0603(1608)_L 133.4,73.5 r270 top (schematic designator R45)
R45_Low "100" RESC0603(1608)_L 75.4,36.5 r90 top (schematic designator R45)
R46_High "100" RESC0603(1608)_L 135.1,73.5 r270 top (schematic designator R46)
R46_Low "100" RESC0603(1608)_L 73.7,36.5 r90 top (schematic designator R46)
R47_High "100" RESC0603(1608)_L 136.8,73.5 r270 top (schematic designator R47)
R47_Low "100" RESC0603(1608)_L 72,36.5 r90 top (schematic designator R47)
R48_High "100" RESC0603(1608)_L 138.5,73.5 r270 top (schematic designator R48)
R48_Low "100" RESC0603(1608)_L 70.3,36.5 r90 top (schematic designator R48)
R49_High "RMCP2010FT20R0" RESC5025X70N 156.779,52.371 r180 bottom value=20 (schematic designator R49)
R49_Low "RMCP2010FT20R0" RESC5025X70N 52,58.2 r0 bottom value=20 (schematic designator R49)
R50_High "RMCP2010FT20R0" RESC5025X70N 156.779,48.271 r180 bottom value=20 (schematic designator R50)
R50_Low "RMCP2010FT20R0" RESC5025X70N 52,62.3 r0 bottom value=20 (schematic designator R50)
R51_High "RMCP2010FT20R0" RESC5025X70N 156.779,44.171 r180 bottom value=20 (schematic designator R51)
R51_Low "RMCP2010FT20R0" RESC5025X70N 52,66.4 r0 bottom value=20 (schematic designator R51)
R52_High "RMCP2010FT20R0" RESC5025X70N 156.779,40.071 r180 bottom value=20 (schematic designator R52)
R52_Low "RMCP2010FT20R0" RESC5025X70N 52,70.5 r0 bottom value=20 (schematic designator R52)
R53_High "RMCP2010FT20R0" RESC5025X70N 156.779,35.971 r180 bottom value=20 (schematic designator R53)
R53_Low "RMCP2010FT20R0" RESC5025X70N 52,74.6 r0 bottom value=20 (schematic designator R53)
R54_High "RMCP2010FT20R0" RESC5025X70N 140.079,35.371 r90 bottom value=20 (schematic designator R54)
R54_Low "RMCP2010FT20R0" RESC5025X70N 68.7,75.2 r270 bottom value=20 (schematic designator R54)
R55_High "RMCP2010FT20R0" RESC5025X70N 135.979,35.371 r90 bottom value=20 (schematic designator R55)
R55_Low "RMCP2010FT20R0" RESC5025X70N 72.8,75.2 r270 bottom value=20 (schematic designator R55)
R56_High "100" RESC0603(1608)_L 140.2,73.5 r270 top (schematic designator R56)
R56_Low "100" RESC0603(1608)_L 68.6,36.5 r90 top (schematic designator R56)
R57_High "100" RESC0603(1608)_L 141.9,73.5 r270 top (schematic designator R57)
R57_Low "100" RESC0603(1608)_L 66.9,36.5 r90 top (schematic designator R57)
R58_High "100" RESC0603(1608)_L 143.6,73.5 r270 top (schematic designator R58)
R58_Low "100" RESC0603(1608)_L 65.2,36.5 r90 top (schematic designator R58)
R59_High "100" RESC0603(1608)_L 145.3,73.5 r270 top (schematic designator R59)
R59_Low "100" RESC0603(1608)_L 63.5,36.5 r90 top (schematic designator R59)
R60_High "100" RESC0603(1608)_L 147,73.5 r270 top (schematic designator R60)
R60_Low "100" RESC0603(1608)_L 61.8,36.5 r90 top (schematic designator R60)
R61_High "100" RESC0603(1608)_L 148.7,73.5 r270 top (schematic designator R61)
R61_Low "100" RESC0603(1608)_L 60.1,36.5 r90 top (schematic designator R61)
R62_High "100" RESC0603(1608)_L 150.4,73.5 r270 top (schematic designator R62)
R62_Low "100" RESC0603(1608)_L 58.4,36.5 r90 top (schematic designator R62)
R63_High "ESR18EZPJ331" FP-ESR18-IPC_A 161.2,37.1 r180 top (schematic designator R63)
R63_Low "ESR18EZPJ331" FP-ESR18-IPC_A 47.6,73.5 r0 top (schematic designator R63)
R64 "RMCF0603FT10R0" RESC0603(1608)_L 79.4,68 r90 top value=10
R64 "RMCF0603FT10R0" RESC0603(1608)_L 129.6,42.5 r270 top value=10
R65_High "ESR03EZPJ102" RESC0603(1608)_L 134.879,40.371 r90 top value=1k (schematic designator R65)
R65_Low "ESR03EZPJ102" RESC0603(1608)_L 73.9,70.2 r270 top value=1k (schematic designator R65)
R66_High "ESR03EZPJ102" RESC0603(1608)_L 133.579,40.371 r90 top value=1k (schematic designator R66)
R66_Low "ESR03EZPJ102" RESC0603(1608)_L 75.2,70.2 r270 top value=1k (schematic designator R66)
R67 "ESR03EZPJ470" RESC0603(1608)_L 85.2,48.7 r180 top value=47
R68 "ESR03EZPJ470" RESC0603(1608)_L 83.3,47.3 r90 top value=47
R69 "RMCF0603ZT0R00" RESC0603(1608)_L 92.5,49.8 r180 top value=0
R70 "ESR03EZPJ470" RESC0603(1608)_L 83.3,43.7 r90 top value=47
R71 "RMCF0603ZT0R00" RESC0603(1608)_L 92.5,44.6 r180 top value=0
R72 "ESR03EZPJ470" RESC0603(1608)_L 85.2,42.3 r180 top value=47
R73 "ESR03EZPJ470" RESC0603(1608)_L 90.079,54.471 r90 top value=47
R74 "ESR03EZPJ470" RESC0603(1608)_L 90.079,56.871 r90 top value=47
R75 "ESR03EZPJ470" RESC0603(1608)_L 91.979,53.771 r180 top value=47
R76 "ESR03EZPJ470" RESC0603(1608)_L 91.979,57.571 r180 top value=47
R77 "ESR03EZPJ470" RESC0603(1608)_L 119.4,67.8 r180 top value=47
R78 "ESR03EZPJ470" RESC0603(1608)_L 119.4,66.5 r180 top value=47
R79 "ESR03EZPJ470" RESC0603(1608)_L 122.7,68.4 r270 top value=47
R80 "ESR03EZPJ470" RESC0603(1608)_L 122.7,65.9 r90 top value=47
R81 "ESR03EZPJ470" RESC0603(1608)_L 123,61.1 r0 top value=47
R82 "ESR03EZPJ470" RESC0603(1608)_L 124.9,60.1 r90 top value=47
R83 "RMCF0603ZT0R00" RESC0603(1608)_L 113.4,60 r0 top value=0
R84 "RMCF0603ZT0R00" RESC0603(1608)_L 113.4,54.8 r0 top value=0
R85 "ESR03EZPJ470" RESC0603(1608)_L 124.9,57.6 r90 top value=47
R86 "ESR03EZPJ470" RESC0603(1608)_L 123,56.6 r0 top value=47

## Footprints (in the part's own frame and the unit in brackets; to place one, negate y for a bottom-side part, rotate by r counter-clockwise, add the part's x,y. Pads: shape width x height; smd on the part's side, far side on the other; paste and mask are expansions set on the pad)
CAPC0603(1608)100_L [mm] "Chip Capacitor, Body 1.6x0.8mm, Height 1.0mm, IPC High Density"
  rrect25% 0.66x0.76 smd: 1(-0.7,0) 2(0.7,0)
  silkscreen extent 0,-0.3 0,0.3, body extent -0.8,-0.4 0.8,0.4, height 0.95
CAPC0805(2012)145_L [mm] "Chip Capacitor, Body 2.0x1.2mm, Height 1.45mm, IPC High Density"
  rrect25% 0.76x1.3 smd: 1(-0.9,0) 2(0.89,0)
  silkscreen extent -0.13,-0.51 0.13,0.51, body extent -1,-0.6 1,0.6, height 1.45
FP-C3225-250-0_4-IPC_B [mm]
  rect 0.953x2.804 smd paste+0 mask+0: 1(-1.675,0) 2(1.675,0)
  silkscreen extent -0.9,-1.4 0.9,1.4, body extent -2.4,-1.65 2.4,1.65, height 0.25
FP-CLM3C-AKW-MFG [mm]
  rect 1.55x2.2 smd paste+0 mask+0: 1(-1.425,0) 2(1.425,0)
  silkscreen extent -3.5,-1.05 0.28,1.05, body extent -2.3,-1.2 2.3,1.2, height 0.25
FP-DLW43-0_2-t2_6-e0_6-MFG [mm]
  rect 1.35x0.9 smd paste+0 mask+0: 1(-2.275,-1.25) 2(2.275,-1.25) 3(2.275,1.25) 4(-2.275,1.25)
  silkscreen extent -3.65,-1.7 2.35,1.7, body extent -3.05,-1.8 3.05,1.8, height 0.25
FP-ESR18-IPC_A [mm]
  rect 1.456x1.858 smd paste+0 mask+0: 1(-1.501,0) 2(1.501,0)
  silkscreen extent -0.47,-0.93 0.47,0.93, body extent -2.73,-1.43 2.73,1.43, height 0.25
MJD31CAJ [mm]
  rect 1.4x2.4 smd: 1(-2.285,-4.1) 3(2.285,-4.1)
  rect 5.9x5.75 smd: 2(0,2.425)
  silkscreen extent -3.3,-5.85 3.3,4.15, body extent -3.3,-5 3.3,5, height 2.38
QFP50P1400X1400X160-81N [mm]
  rect 1.475x0.3 smd: 1(-6.738,4.75) 2(-6.738,4.25) 3(-6.738,3.75) 4(-6.738,3.25) 5(-6.738,2.75) 6(-6.738,2.25) 7(-6.738,1.75) 8(-6.738,1.25) 9(-6.738,0.75) 10(-6.738,0.25) 11(-6.738,-0.25) 12(-6.738,-0.75) 13(-6.738,-1.25) 14(-6.738,-1.75) 15(-6.738,-2.25) 16(-6.738,-2.75) 17(-6.738,-3.25) 18(-6.738,-3.75) 19(-6.738,-4.25) 20(-6.738,-4.75) 41(6.738,-4.75) 42(6.738,-4.25) 43(6.738,-3.75) 44(6.738,-3.25) 45(6.738,-2.75) 46(6.738,-2.25) 47(6.738,-1.75) 48(6.738,-1.25) 49(6.738,-0.75) 50(6.738,-0.25) 51(6.738,0.25) 52(6.738,0.75) 53(6.738,1.25) 54(6.738,1.75) 55(6.738,2.25) 56(6.738,2.75) 57(6.738,3.25) 58(6.738,3.75) 59(6.738,4.25) 60(6.738,4.75)
  rect 0.3x1.475 smd: 21(-4.75,-6.738) 22(-4.25,-6.738) 23(-3.75,-6.738) 24(-3.25,-6.738) 25(-2.75,-6.738) 26(-2.25,-6.738) 27(-1.75,-6.738) 28(-1.25,-6.738) 29(-0.75,-6.738) 30(-0.25,-6.738) 31(0.25,-6.738) 32(0.75,-6.738) 33(1.25,-6.738) 34(1.75,-6.738) 35(2.25,-6.738) 36(2.75,-6.738) 37(3.25,-6.738) 38(3.75,-6.738) 39(4.25,-6.738) 40(4.75,-6.738) 61(4.75,6.738) 62(4.25,6.738) 63(3.75,6.738) 64(3.25,6.738) 65(2.75,6.738) 66(2.25,6.738) 67(1.75,6.738) 68(1.25,6.738) 69(0.75,6.738) 70(0.25,6.738) 71(-0.25,6.738) 72(-0.75,6.738) 73(-1.25,6.738) 74(-1.75,6.738) 75(-2.25,6.738) 76(-2.75,6.738) 77(-3.25,6.738) 78(-3.75,6.738) 79(-4.25,6.738) 80(-4.75,6.738)
  rect 5.91x5.91 smd: 81(0,0)
  silkscreen extent -7.35,5.37 -7.1,5.62, body extent -7,-7 7,7, height 1.6
RESC0603(1608)_L [mm] "Chip Resistor, Body 1.6x0.8mm, IPC High Density"
  rrect25% 0.66x0.76 smd: 1(-0.7,0) 2(0.7,0)
  silkscreen extent 0,-0.3 0,0.3, body extent -0.8,-0.4 0.8,0.4, height 0.45
RESC5025X70N [mm]
  rect 1.33x2.72 smd: 1(-2.294,0) 2(2.294,0)
  silkscreen extent -1.31,-1.35 1.31,1.35, body extent -2.5,-1.25 2.5,1.25, height 0.7
SHDR4W50P200_2X2_600X500X660P [mm]
  rect 1.35x1.35 hole 0.9: 1(0,0)
  round 1.35 hole 0.9: 2(0,2) 3(-2,0) 4(-2,2)
  silkscreen extent -4,-1.5 2,3.5, body extent -4,-1.5 2,3.5, height 6.6
SMD-0603 [mm] "Chip Inductor, 2-Leads, Body 1.6x0.8mm"
  rect 0.85x0.7 smd: 1(-0.775,0) 2(0.775,0)
  body extent -0.8,-0.4 0.8,0.4, height 0.79
SOD2613X114N [mm]
  rect 1.075x0.5 smd: 1(-1.15,0) 2(1.15,0)
  silkscreen extent -1.69,-0.65 0.88,0.65, body extent -1.29,-0.65 1.29,0.65, height 1.14
TFM12002LDATR [mm]
  rect 0.74x2.92 smd: 1(-12.065,-1.715) 2(-12.065,1.715) 3(-10.795,-1.715) 4(-10.795,1.715) 5(-9.525,-1.715) 6(-9.525,1.715) 7(-8.255,-1.715) 8(-8.255,1.715) 9(-6.985,-1.715) 10(-6.985,1.715) 11(-5.715,-1.715) 12(-5.715,1.715) 13(-4.445,-1.715) 14(-4.445,1.715) 15(-3.175,-1.715) 16(-3.175,1.715) 17(-1.905,-1.715) 18(-1.905,1.715) 19(-0.635,-1.715) 20(-0.635,1.715) 21(0.635,-1.715) 22(0.635,1.715) 23(1.905,-1.715) 24(1.905,1.715) 25(3.175,-1.715) 26(3.175,1.715) 27(4.445,-1.715) 28(4.445,1.715) 29(5.715,-1.715) 30(5.715,1.715) 31(6.985,-1.715) 32(6.985,1.715) 33(8.255,-1.715) 34(8.255,1.715) 35(9.525,-1.715) 36(9.525,1.715) 37(10.795,-1.715) 38(10.795,1.715) 39(12.065,-1.715) 40(12.065,1.715)
  round 0.71 hole 1.42 unplated: MH1(-13.655,0) MH2(13.655,0)
  silkscreen extent -14.29,-3.9 14.29,2.86, body extent -14.29,-3.1 14.29,3.1, height 5.99
WL-SMCW_0603_150060xx75000 [mm] "SMD Mono-color Chip LED, body 1.6x0.8mm"
  rect 0.8x0.8 smd: 1(-0.8,0) 2(0.8,0)
  silkscreen extent -1.55,-0.4 -1.4,0.4, body extent -0.8,-0.4 0.8,0.4, height 0.7

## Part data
BMS_IC1_High BMS_IC1_Low: "Integrated Circuit", Manufacturer_Name="Analog Devices", Mouser Part Number=584-ADBMS6830BCSWZ
C1_High C1_Low C2_High C2_Low C3_High C3_Low C4_High C4_Low C5_High C5_Low C6_High C6_Low C7_High C7_Low C8_High C8_Low C9_High C9_Low C10_High C10_Low C25_High C25_Low C26_High C26_Low C27_High C27_Low C28_High C28_Low C29_High C29_Low C30_High C30_Low C31_High C31_Low C32_High C32_Low C33_High C33_Low C34_High C34_Low C35_High C35_Low C36_High C36_Low C37_High C37_Low C38_High C38_Low C48 C51 C56 C61: library part CMP-002-00083-1, "Ceramic Capacitor, Multilayer, Ceramic, 100V, 10% +Tol, 10% -Tol, X7R, 15% TC, 0.1uF, Surface Mount, 0603 GCJ188R72A104KA01D", Case/Package=0603, Max Operating Temperature=125°C, Min Operating Temperature=-55°C
C11_High C11_Low C12_High C12_Low C13_High C13_Low C14_High C14_Low C15_High C15_Low C16_High C16_Low C17_High C17_Low C18_High C18_Low C19_High C19_Low C20_High C20_Low C21_High C21_Low C22_High C22_Low C23_High C23_Low C24_High C24_Low C39_High C39_Low C43_High C43_Low C44_High C44_Low C45_High C45_Low: library part CMP-009-00202-1, "Ceramic Capacitor, Multilayer, Ceramic, 100V, 10% +Tol, 10% -Tol, X7R, 15% TC, 0.01uF, Surface Mount, 0603", Case/Package=0603, Max Operating Temperature=125°C, Min Operating Temperature=-55°C
C40_High C40_Low C41_High C41_Low C42_High C42_Low: library part CMP-001-00123-1, "Ceramic Capacitor, Multilayer, Ceramic, 100V, 10% +Tol, 10% -Tol, X7S, 22% TC, 1uF, Surface Mount, 0805 / HMK212BC7105KGHTE", Capacitor Type=Ceramic
C46 C50 C52 C53 C57 C58 C59 C63: library part CMP-001-00103-1, "Ceramic Capacitor, Multilayer, Ceramic, 100V, 5% +Tol, 5% -Tol, C0G, -/+30ppm/Cel TC, 0.00022uF, Surface Mount, 0603", Capacitor Type=Ceramic, Case/Package=0603, Max Operating Temperature=125°C, Min Operating Temperature=-55°C
C47 C49 C54 C55 C60 C62: library part CMP-08246-005724-1, "Multilayer Ceramic Capacitors 22nF ±5% 1000V C0G SMD 1210", Capacitance=22nF, Case Code (Imperial)=1210, Case Code (Metric)=3225, Max Operating Temperature=125°C, Min Operating Temperature=-55°C, Tolerance=5%, Voltage Rating=1kV
D1_High D1_Low D2_High D2_Low D3_High D3_Low D4_High D4_Low D5_High D5_Low D6_High D6_Low D7_High D7_Low D8_High D8_Low D9_High D9_Low D10_High D10_Low D11_High D11_Low D12_High D12_Low D13_High D13_Low D14_High D14_Low: library part CMP-1426-00001-3, Case Code (Imperial)=0603, Case Code (Metric)=1608, Color=Red, Forward Current=100mA, Forward Voltage=2V, Max Junction Temperature (Tj)=95°C, Max Operating Temperature=85°C, Max Reverse Voltage (DC)=5V, Min Operating Temperature=-40°C, Power Dissipation=72mW, Test Current=20mA
D15_High D15_Low: library part CMP-13977-000023-1, "LED AMBER CLEAR 2PLCC SMD", Case/Package=PLCC, Color=Orange, Forward Current=20mA, Forward Voltage=2.1V, Lens Color=Colorless, Max Operating Temperature=100°C, Min Operating Temperature=-40°C, Package Quantity=2500, Power Dissipation=130mW, Reverse Voltage=5V
D16 D17 D18 D19: "TVS Diode (Bi-directional)", Manufacturer_Name=LITTELFUSE, Mouser Part Number=576-SD12C-01FTG
J1_High J1_Low: "Connector", Manufacturer_Name=SAMTEC
J2 J3: "Connector", Arrow Part Number=DF11-4DP-2DSA(01), Manufacturer_Name=Hirose, Mouser Part Number=798-DF11-4DP-2DSA01
L1_High L1_Low: library part CMP-0220-00111-1, "SMD EMI Suppression Ferrite Bead WE-CBF, Z = 2200 Ohm"
L2 L3: library part CMP-06045-000059-1, "CMC 100UH 200MA 2LN SMD AEC-Q200", Case Code (Imperial)=1812, Case Code (Metric)=4532, Current=200mA, DC Resistance (DCR)=2R, Inductance=100uH, Max Operating Temperature=125°C, Min Operating Temperature=-40°C, Package Quantity=1, Test Frequency=1MHz, Tolerance=50%, Voltage Rating=50V
Q1_High Q1_Low: "Transistor BJT NPN", Manufacturer_Name=Nexperia, Mouser Part Number=771-MJD31CAJ
R1_High R1_Low R2_High R2_Low R34_High R34_Low R69 R71 R83 R84: library part CMP-009-00243-1, "Fixed Resistor, Metal Glaze/thick Film, 0.1W, 0ohm, Surface Mount, 0603", Case/Package=0603, Max Operating Temperature=155°C, Min Operating Temperature=-55°C, Power=100mW
R3_High R3_Low R4_High R4_Low R5_High R5_Low R6_High R6_Low R7_High R7_Low R8_High R8_Low R9_High R9_Low R10_High R10_Low R11_High R11_Low R12_High R12_Low: library part CMP-009-00204-1, "Fixed Resistor, Thin Film, 0.1W, 10000ohm, 75V, 0.1% +/-Tol, 25ppm/Cel, Surface Mount, 0603", Case/Package=0603, Max Operating Temperature=155°C, Min Operating Temperature=-55°C, Power=100mW, Tolerance=0.1%
R13_High R13_Low R14_High R14_Low R15_High R15_Low R16_High R16_Low R17_High R17_Low R18_High R18_Low R19_High R19_Low R20_High R20_Low R21_High R21_Low R22_High R22_Low R23_High R23_Low R24_High R24_Low R25_High R25_Low R26_High R26_Low R27_High R27_Low R28_High R28_Low R29_High R29_Low R30_High R30_Low R31_High R31_Low R32_High R32_Low R33_High R33_Low: library part CMP-009-00201-1, "Fixed Resistor, Metal Glaze/thick Film, 0.25W, 200ohm, 150V, 1% +/-Tol, 100ppm/Cel, Surface Mount, 0603", Case/Package=0603, Max Operating Temperature=155°C, Min Operating Temperature=-55°C, Power=250mW, Tolerance=1%
R35_High R35_Low R36_High R36_Low R37_High R37_Low R38_High R38_Low R39_High R39_Low R40_High R40_Low R41_High R41_Low R49_High R49_Low R50_High R50_Low R51_High R51_Low R52_High R52_Low R53_High R53_Low R54_High R54_Low R55_High R55_Low: "20 Ohms Â±1% 1W Chip Resistor 2010 (5025 Metric) Automotive AEC-Q200 Thick Film", Package="5025 Stackpole"
R42_High R42_Low R43_High R43_Low R44_High R44_Low R45_High R45_Low R46_High R46_Low R47_High R47_Low R48_High R48_Low R56_High R56_Low R57_High R57_Low R58_High R58_Low R59_High R59_Low R60_High R60_Low R61_High R61_Low R62_High R62_Low: library part CMP-009-00197-1, "100 Ohm Resistor, 150 V, 1/4W, 0603, ESR03EZPF1000"
R63_High R63_Low: library part CMP-08839-029435-1, "330Ω ±5% 0.5W 1206 Anti-Surge Chip Resistor AEC-Q200", Case Code (Imperial)=1206, Case Code (Metric)=3216, Max Operating Temperature=155°C, Max Power Dissipation=333mW, Min Operating Temperature=-55°C, Package Quantity=1, Resistance=330, Resistor Type="Thick Film", Temperature Coefficient=200ppm/°C, Tolerance=5%
R64 R64: library part CMP-009-00205-1, "Fixed Resistor, Metal Glaze/thick Film, 0.1W, 10ohm, 75V, 1% +/-Tol, 100ppm/Cel, Surface Mount, 0603", Case/Package=0603, Max Operating Temperature=155°C, Min Operating Temperature=-55°C, Power=100mW, Tolerance=1%
R65_High R65_Low R66_High R66_Low: library part CMP-009-00207-1, "Fixed Resistor, Metal Glaze/thick Film, 0.25W, 1000ohm, 150V, 5% +/-Tol, 200ppm/Cel, Surface Mount, 0603", Case/Package=0603, Max Operating Temperature=155°C, Min Operating Temperature=-55°C, Power=250mW, Tolerance=5%
R67 R68 R70 R72 R73 R74 R75 R76 R77 R78 R79 R80 R81 R82 R85 R86: library part CMP-009-00206-1, "Fixed Resistor, Metal Glaze/thick Film, 0.25W, 47ohm, 150V, 5% +/-Tol, 200ppm/Cel, Surface Mount, 0603", Case/Package=0603, Max Operating Temperature=155°C, Min Operating Temperature=-55°C, Power=250mW, Tolerance=5%

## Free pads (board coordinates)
  round 0 hole 4.32: 1(40,34) 1(40,75.91) 1(105,34) 1(105,75.91) 1(169.54,34) 1(169.54,75.91)

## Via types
v1: diameter 0.45, hole 0.2, Top Layer to Bottom Layer, tented both sides, 226 vias
v2: diameter 0.5, hole 0.2, Top Layer to Bottom Layer, tented both sides, 105 vias
v3: diameter 2, hole 0.5, Top Layer to Bottom Layer, tented both sides, 2 vias

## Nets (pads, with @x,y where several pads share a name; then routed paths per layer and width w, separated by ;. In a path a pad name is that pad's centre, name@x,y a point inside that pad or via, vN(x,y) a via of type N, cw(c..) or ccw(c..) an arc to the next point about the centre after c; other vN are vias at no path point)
Base_High: Q1_High.1 R64.2@129.6,41.8 | length 3.5
  Top Layer w0.6: Q1_High.1@126.771,42.679 Q1_High.1@126.764,42.671 126.764,42.2 127.164,41.8 R64.2@129.6,41.8 ; R64.2@129.593,41.807 R64.2@129.6,41.8 ; R64.2@129.6,41.8 129.592,41.792 R64.2@129.6,41.8
Base_Low: Q1_Low.1 R64.2@79.4,68.7 | length 3.2
  Top Layer w0.6: R64.2@79.408,68.693 R64.2@79.4,68.7 ; Q1_Low.1@82.008,67.893 Q1_Low.1@82.015,67.9 82.015,68.3 81.615,68.7 R64.2@79.4,68.7 ; R64.2@79.4,68.7 79.408,68.708 R64.2@79.4,68.7
C1_High: BMS_IC1_High.57 C11_High.1 R13_High.2 | length 6.8
  Top Layer w0.3: BMS_IC1_High.57@135.05,57.438 135.05,62.843 C11_High.1@135.179,62.971 135.179,64.071 R13_High.2@135.279,64.171
C1_Low: BMS_IC1_Low.57 C11_Low.1 R13_Low.2 | length 6.8
  Top Layer w0.3: R13_Low.2@73.5,46.4 73.6,46.5 C11_Low.1@73.6,47.6 73.729,47.729 BMS_IC1_Low.57@73.729,53.133
C2:1_High: BMS_IC1_High.54 C11_High.2 C12_High.1 R14_High.2 | length 6.7
  Top Layer w0.3: BMS_IC1_High.54@136.55,57.438 C12_High.1@136.55,61.671 ; C12_High.1@136.579,61.671 C11_High.2@136.579,62.971 R14_High.2@136.579,64.171
C2:1_Low: BMS_IC1_Low.54 C11_Low.2 C12_Low.1 R14_Low.2 | length 6.7
  Top Layer w0.3: R14_Low.2@72.2,46.4 C11_Low.2@72.2,47.6 C12_Low.1@72.2,48.9 ; C12_Low.1@72.229,48.9 BMS_IC1_Low.54@72.229,53.133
